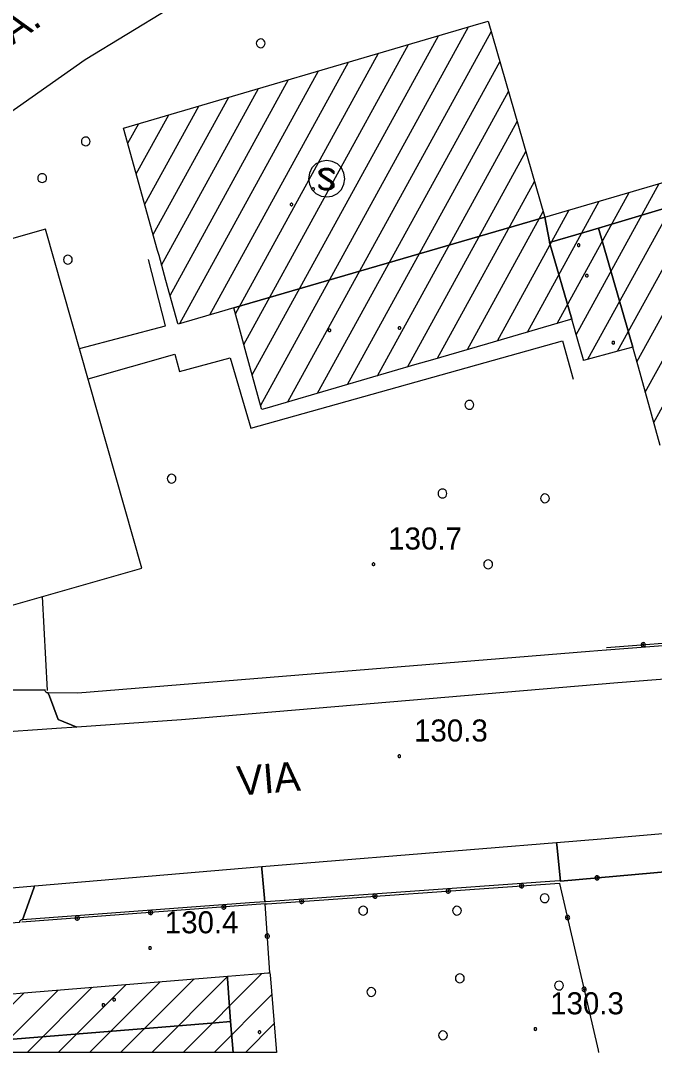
# Model space of a CAD drawing. Extents: x 513373 to 514978, y 5038576 to 5040180.
# Drawn here: x 513408.3 to 513451.4, y 5038580.1 to 5038650.3 of the extents above; entities that cross this region are included whole.
import ezdxf

# ---------------------------------------------------------------- set-up
doc = ezdxf.new("R2010")
doc.units = 0
for name, color, linetype in [('2010300', 7, 'Continuous'), ('3010204', 7, 'Continuous'), ('3030201', 7, 'Continuous'), ('3060104', 7, 'Continuous'), ('B1211', 7, 'Continuous'), ('C1131', 7, 'Continuous'), ('C12211', 7, 'Continuous'), ('C2911', 7, 'Continuous'), ('CAMP_C12211', 7, 'Continuous'), ('Default', 7, 'Continuous'), ('F12107', 7, 'Continuous'), ('F12131', 7, 'Continuous'), ('F12132', 7, 'Continuous'), ('G4315', 7, 'Continuous'), ('TOP500', 7, 'Continuous'), ('TOP920', 7, 'Continuous')]:
    doc.layers.add(name, color=color, linetype=linetype)

# ---------------------------------------------------------------- blocks, each defined once
blk = doc.blocks.new('CAMP_1CE415D7')
at = {"layer": 'CAMP_C12211'}
for p, q in [((2.937, -2.063), (7.928, 2.928)), ((5.058, -2.063), (10.238, 3.116)), ((7.18, -2.063), (12.549, 3.306)), ((-5.548, -2.063), (-1.311, 2.174)), ((-3.427, -2.063), (0.999, 2.362)), ((-1.306, -2.063), (3.309, 2.551)), ((0.816, -2.063), (5.618, 2.739)), ((-11.619, 0.351), (-10.551, 1.42)), ((-11.442, -1.593), (-8.241, 1.608)), ((-9.791, -2.063), (-5.931, 1.797)), ((-7.669, -2.063), (-3.621, 1.986)), ((9.301, -2.063), (13.227, 1.863)), ((11.422, -2.063), (13.385, -0.1)), ((-11.912, -2.063), (-11.599, -1.75))]:
    blk.add_line(p, q, dxfattribs=at)
blk = doc.blocks.new('CAMP_2F84D089')
at = {"layer": 'CAMP_C12211'}
for p, q in [((-57.724, -31.968), (-43.578, -6.238)), ((-58.296, -29.896), (-45.619, -6.835)), ((-55.887, -31.74), (-42.047, -6.566)), ((-58.869, -27.824), (-47.659, -7.433)), ((-59.441, -25.752), (-49.699, -8.031)), ((-61.191, -25.821), (-51.74, -8.629)), ((-53.849, -31.147), (-41.456, -8.604)), ((-63.23, -26.415), (-53.78, -9.227)), ((-64.463, -22.431), (-57.861, -10.422)), ((-63.889, -24.5), (-55.821, -9.824)), ((-65.037, -20.361), (-59.901, -11.02)), ((-51.811, -30.553), (-40.865, -10.642)), ((-65.611, -18.292), (-61.942, -11.618)), ((-66.185, -16.222), (-63.982, -12.216)), ((-66.759, -14.153), (-66.022, -12.813)), ((-49.772, -29.959), (-40.273, -12.68)), ((-30.984, -33.147), (-20.405, -13.904)), ((-47.734, -29.365), (-39.682, -14.718)), ((-31.557, -31.075), (-22.446, -14.502)), ((-32.13, -29.004), (-24.486, -15.099)), ((-33.448, -28.287), (-26.526, -15.697)), ((-45.696, -28.772), (-39.091, -16.756)), ((-35.462, -28.837), (-28.566, -16.294)), ((-37.544, -26.397), (-32.647, -17.489)), ((-36.258, -27.171), (-30.606, -16.892)), ((-39.582, -26.99), (-34.687, -18.087)), ((-43.658, -28.178), (-38.499, -18.794)), ((-41.62, -27.584), (-36.727, -18.684))]:
    blk.add_line(p, q, dxfattribs=at)
blk = doc.blocks.new('03080200')
at = {"layer": 'Default'}
for p, q in [((-0.139, 0.046), (-0.146, 0)), ((-0.146, 0), (-0.139, -0.046)), ((-0.118, 0.086), (-0.139, 0.046)), ((-0.086, 0.118), (-0.118, 0.086)), ((-0.046, 0.139), (-0.086, 0.118)), ((0, 0.146), (-0.046, 0.139)), ((-0.042, 0.014), (-0.045, 0)), ((-0.045, 0), (-0.042, -0.014)), ((-0.036, 0.026), (-0.042, 0.014)), ((-0.026, 0.036), (-0.036, 0.026)), ((-0.014, 0.042), (-0.026, 0.036)), ((0, 0.045), (-0.014, 0.042)), ((0.046, 0.139), (0, 0.146)), ((0.014, 0.042), (0, 0.045)), ((0.026, 0.036), (0.014, 0.042)), ((0.036, 0.026), (0.026, 0.036)), ((0.042, 0.014), (0.036, 0.026)), ((0.045, 0), (0.042, 0.014)), ((0.042, -0.014), (0.045, 0)), ((0.086, 0.118), (0.046, 0.139)), ((0.118, 0.086), (0.086, 0.118)), ((0.139, 0.046), (0.118, 0.086)), ((0.146, 0), (0.139, 0.046)), ((0.139, -0.046), (0.146, 0)), ((-0.139, -0.046), (-0.118, -0.086)), ((-0.118, -0.086), (-0.086, -0.118)), ((-0.086, -0.118), (-0.046, -0.139)), ((-0.046, -0.139), (0, -0.146)), ((-0.042, -0.014), (-0.036, -0.026)), ((-0.036, -0.026), (-0.026, -0.036)), ((-0.026, -0.036), (-0.014, -0.042)), ((-0.014, -0.042), (0, -0.045)), ((0, -0.045), (0.014, -0.042)), ((0, -0.146), (0.046, -0.139)), ((0.014, -0.042), (0.026, -0.036)), ((0.026, -0.036), (0.036, -0.026)), ((0.036, -0.026), (0.042, -0.014)), ((0.046, -0.139), (0.086, -0.118)), ((0.086, -0.118), (0.118, -0.086)), ((0.118, -0.086), (0.139, -0.046))]:
    blk.add_line(p, q, dxfattribs=at)
blk = doc.blocks.new('08020400')
at = {"layer": 'Default'}
for p, q in [((-0.086, 0.028), (-0.09, 0)), ((-0.09, 0), (-0.086, -0.028)), ((-0.073, 0.053), (-0.086, 0.028)), ((-0.053, 0.073), (-0.073, 0.053)), ((-0.028, 0.086), (-0.053, 0.073)), ((0, 0.09), (-0.028, 0.086)), ((0.028, 0.086), (0, 0.09)), ((0.053, 0.073), (0.028, 0.086)), ((0.073, 0.053), (0.053, 0.073)), ((0.086, 0.028), (0.073, 0.053)), ((0.09, 0), (0.086, 0.028)), ((0.086, -0.028), (0.09, 0)), ((-0.086, -0.028), (-0.073, -0.053)), ((-0.073, -0.053), (-0.053, -0.073)), ((-0.053, -0.073), (-0.028, -0.086)), ((-0.028, -0.086), (0, -0.09)), ((0, -0.09), (0.028, -0.086)), ((0.028, -0.086), (0.053, -0.073)), ((0.053, -0.073), (0.073, -0.053)), ((0.073, -0.053), (0.086, -0.028))]:
    blk.add_line(p, q, dxfattribs=at)
blk = doc.blocks.new('NSIMB25')
at = {"layer": 'Default'}
for p, q in [((-0.086, 0.028), (-0.09, 0)), ((-0.09, 0), (-0.086, -0.028)), ((-0.073, 0.053), (-0.086, 0.028)), ((-0.053, 0.073), (-0.073, 0.053)), ((-0.028, 0.086), (-0.053, 0.073)), ((0, 0.09), (-0.028, 0.086)), ((0.028, 0.086), (0, 0.09)), ((0.053, 0.073), (0.028, 0.086)), ((0.073, 0.053), (0.053, 0.073)), ((0.086, 0.028), (0.073, 0.053)), ((0.09, 0), (0.086, 0.028)), ((0.086, -0.028), (0.09, 0)), ((-0.086, -0.028), (-0.073, -0.053)), ((-0.073, -0.053), (-0.053, -0.073)), ((-0.053, -0.073), (-0.028, -0.086)), ((-0.028, -0.086), (0, -0.09)), ((0, -0.09), (0.028, -0.086)), ((0.028, -0.086), (0.053, -0.073)), ((0.053, -0.073), (0.073, -0.053)), ((0.073, -0.053), (0.086, -0.028))]:
    blk.add_line(p, q, dxfattribs=at)
blk = doc.blocks.new('05010100')
at = {"layer": 'Default'}
for p, q in [((-0.143, 0.046), (-0.15, 0)), ((-0.15, 0), (-0.143, -0.046)), ((-0.121, 0.088), (-0.143, 0.046)), ((-0.088, 0.121), (-0.121, 0.088)), ((-0.046, 0.143), (-0.088, 0.121)), ((0, 0.15), (-0.046, 0.143)), ((0.046, 0.143), (0, 0.15)), ((0.088, 0.121), (0.046, 0.143)), ((0.121, 0.088), (0.088, 0.121)), ((0.143, 0.046), (0.121, 0.088)), ((0.15, 0), (0.143, 0.046)), ((0.143, -0.046), (0.15, 0)), ((-0.143, -0.046), (-0.121, -0.088)), ((-0.121, -0.088), (-0.088, -0.121)), ((-0.088, -0.121), (-0.046, -0.143)), ((-0.046, -0.143), (0, -0.15)), ((0, -0.15), (0.046, -0.143)), ((0.046, -0.143), (0.088, -0.121)), ((0.088, -0.121), (0.121, -0.088)), ((0.121, -0.088), (0.143, -0.046))]:
    blk.add_line(p, q, dxfattribs=at)
blk = doc.blocks.new('03030201')
at = {"layer": 'Default'}
for p, q in [((-1.001, 0.728), (-1.177, 0.382)), ((-0.728, 1.001), (-1.001, 0.728)), ((-0.382, 1.177), (-0.728, 1.001)), ((0, 1.237), (-0.382, 1.177)), ((-0.368, 0.643), (-0.158, 0.718)), ((-0.158, 0.718), (0.127, 0.718)), ((0.382, 1.177), (0, 1.237)), ((0.127, 0.718), (0.337, 0.643)), ((0.728, 1.001), (0.382, 1.177)), ((1.001, 0.728), (0.728, 1.001)), ((1.177, 0.382), (1.001, 0.728)), ((-1.177, 0.382), (-1.238, 0)), ((-1.238, 0), (-1.177, -0.382)), ((-0.518, 0.508), (-0.368, 0.643)), ((-0.518, 0.358), (-0.518, 0.508)), ((-0.443, 0.223), (-0.518, 0.358)), ((-0.333, 0.584), (-0.451, 0.478)), ((-0.451, 0.478), (-0.451, 0.376)), ((-0.451, 0.376), (-0.389, 0.265)), ((-0.368, 0.148), (-0.443, 0.223)), ((-0.389, 0.265), (-0.326, 0.201)), ((-0.298, 0.526), (-0.383, 0.448)), ((-0.383, 0.448), (-0.383, 0.394)), ((-0.383, 0.394), (-0.335, 0.306)), ((0.148, -0.186), (-0.368, 0.148)), ((-0.335, 0.306), (-0.287, 0.257)), ((-0.147, 0.651), (-0.333, 0.584)), ((-0.326, 0.201), (0.183, -0.128)), ((-0.135, 0.583), (-0.298, 0.526)), ((-0.287, 0.257), (-0.18, 0.198)), ((-0.18, 0.198), (0.337, -0.137)), ((0.115, 0.651), (-0.147, 0.651)), ((0.103, 0.583), (-0.135, 0.583)), ((0.266, 0.526), (0.103, 0.583)), ((0.301, 0.584), (0.115, 0.651)), ((0.487, 0.327), (0.266, 0.526)), ((0.487, 0.418), (0.301, 0.584)), ((0.337, 0.643), (0.487, 0.508)), ((0.487, 0.508), (0.487, 0.327)), ((1.238, 0), (1.177, 0.382)), ((1.177, -0.382), (1.238, 0)), ((-1.177, -0.382), (-1.001, -0.728)), ((-0.518, -0.39), (-0.298, -0.588)), ((-0.518, -0.572), (-0.518, -0.39)), ((-0.333, -0.647), (-0.518, -0.481)), ((-0.368, -0.707), (-0.518, -0.572)), ((-0.147, -0.714), (-0.333, -0.647)), ((-0.298, -0.588), (-0.135, -0.647)), ((-0.135, -0.647), (0.103, -0.647)), ((0.103, -0.647), (0.266, -0.588)), ((0.301, -0.647), (0.115, -0.714)), ((0.254, -0.245), (0.148, -0.186)), ((0.183, -0.128), (0.295, -0.191)), ((0.302, -0.293), (0.254, -0.245)), ((0.266, -0.588), (0.352, -0.512)), ((0.295, -0.191), (0.357, -0.253)), ((0.419, -0.542), (0.301, -0.647)), ((0.352, -0.382), (0.302, -0.293)), ((0.337, -0.137), (0.412, -0.212)), ((0.487, -0.572), (0.337, -0.707)), ((0.352, -0.512), (0.352, -0.382)), ((0.357, -0.253), (0.419, -0.364)), ((0.412, -0.212), (0.487, -0.347)), ((0.419, -0.364), (0.419, -0.542)), ((0.487, -0.347), (0.487, -0.572)), ((1.001, -0.728), (1.177, -0.382)), ((-1.001, -0.728), (-0.728, -1.001)), ((-0.728, -1.001), (-0.382, -1.177)), ((-0.382, -1.177), (0, -1.238)), ((-0.158, -0.782), (-0.368, -0.707)), ((0.127, -0.782), (-0.158, -0.782)), ((0.115, -0.714), (-0.147, -0.714)), ((0, -1.238), (0.382, -1.177)), ((0.337, -0.707), (0.127, -0.782)), ((0.382, -1.177), (0.728, -1.001)), ((0.728, -1.001), (1.001, -0.728))]:
    blk.add_line(p, q, dxfattribs=at)
blk = doc.blocks.new('A$C3704598A')
at = {"layer": '2010300'}
for points in [[(63.875, -708.514), (65.701, -714.881), (66.154, -716.461), (50.099, -726.135), (45.283, -729.066), (39.595, -732.528), (29.764, -739.427), (17.578, -748.279), (17.196, -748.707), (8.795, -758.134), (8.774, -758.179), (8.768, -758.22), (8.774, -758.259)], [(36.874, -775.359), (36.871, -775.404), (36.88, -775.442), (36.895, -775.472), (36.907, -775.486), (36.914, -775.495), (36.941, -775.516), (36.972, -775.531), (37.005, -775.537), (37.076, -775.539), (39.113, -775.552), (73.91, -772.72), (75.04, -772.628)], [(71.944, -788.357), (71.911, -788.346), (71.882, -788.343), (70.906, -788.412), (51.893, -789.76)]]:
    blk.add_lwpolyline(points, dxfattribs=at)
at = {"layer": '3010204'}
for points in [[(39.213, -752.142), (45.068, -750.604), (43.911, -746.101)], [(39.803, -754.209), (45.701, -752.536), (46.027, -753.7), (49.467, -752.772), (50.865, -757.55), (72.079, -751.622), (72.799, -754.221)], [(36.69, -769.003), (37.019, -775.389)]]:
    blk.add_lwpolyline(points, dxfattribs=at)
at = {"layer": '3060104'}
blk.add_lwpolyline([(23.688, -747.789), (30.258, -770.837), (43.469, -767.071), (36.899, -744.023), (23.688, -747.789)], dxfattribs=at)
at = {"layer": 'B1211'}
blk.add_lwpolyline([(182.854, -779.395), (110.289, -784.942), (71.944, -788.357), (71.695, -785.89), (71.68, -785.737), (74.707, -785.49), (148.809, -779.036), (181.633, -776.874)], dxfattribs=at)
for points in [[(126.207, -770.822), (125.282, -770.893), (121.262, -771.205), (105.455, -772.523), (91.204, -773.673), (75.853, -774.87), (46.166, -777.392), (39.03, -777.882), (37.775, -777.377), (37.169, -775.785), (37.076, -775.539), (39.113, -775.552), (73.91, -772.72), (75.04, -772.628), (75.078, -772.63), (82.766, -772.041), (100.88, -770.652), (125.459, -768.701), (126.353, -768.63), (126.388, -768.62), (126.591, -769.326), (126.566, -770.204)], [(36.874, -775.359), (36.871, -775.404), (36.88, -775.442), (36.895, -775.472), (36.907, -775.486), (36.914, -775.495), (36.941, -775.516), (36.972, -775.531), (37.005, -775.537), (37.076, -775.539), (37.169, -775.785), (37.775, -777.377), (39.03, -777.882), (37.652, -777.977), (33.075, -778.291), (34.323, -775.598), (34.359, -775.521), (34.445, -775.519), (34.49, -775.507), (34.525, -775.485), (34.556, -775.448), (34.572, -775.409), (34.576, -775.359), (35.967, -775.359)], [(71.944, -788.357), (71.911, -788.346), (71.882, -788.343), (70.906, -788.412), (51.893, -789.76), (51.852, -789.755), (51.821, -789.758), (51.629, -787.527), (51.616, -787.372), (71.68, -785.737), (71.695, -785.89)], [(51.821, -789.758), (50.787, -789.835), (35.341, -790.991), (36.103, -788.834), (36.159, -788.677), (51.616, -787.372), (51.629, -787.527)], [(35.341, -790.991), (35.266, -790.997), (35.233, -791.006), (35.199, -791.024), (35.167, -791.055), (35.152, -791.08), (35.141, -791.112), (35.14, -791.17), (34.228, -791.241), (32.804, -791.349), (32.793, -791.289), (32.773, -791.253), (32.74, -791.221), (32.703, -791.202), (32.662, -791.195), (32.594, -791.198), (31.771, -789.207), (31.711, -789.061), (36.159, -788.677), (36.103, -788.834)]]:
    blk.add_lwpolyline(points, close=True, dxfattribs=at)
at = {"layer": 'C1131'}
for points in [[(70.879, -743.211), (69.869, -743.505), (49.715, -749.383), (48.71, -749.676), (47.244, -750.104), (45.921, -750.489), (45.906, -750.435), (45.1, -747.529), (44.628, -745.825), (44.53, -745.472), (42.222, -737.153), (66.009, -730.184), (67.014, -729.89), (70.863, -743.155)], [(112.295, -732.614), (111.902, -732.735), (111.351, -732.904), (98.666, -736.811), (99.057, -738.153), (85.626, -742.147), (85.609, -742.087), (85.22, -740.763), (84.217, -741.064), (74.53, -743.966), (73.524, -744.256), (71.2, -744.928), (71.19, -744.875), (70.879, -743.211), (72.044, -742.87), (110.878, -731.497), (111.883, -731.202), (112.235, -732.406)], [(71.2, -744.928), (72.706, -750.151), (72.62, -750.176), (71.701, -750.444), (66.966, -751.823), (63.085, -752.954), (62.175, -753.219), (51.959, -756.195), (51.624, -756.292), (51.609, -756.238), (50.568, -752.469), (50.168, -751.023), (49.715, -749.383), (69.869, -743.505), (70.879, -743.211), (71.19, -744.875)], [(76.86, -752.044), (75.85, -752.32), (73.515, -752.957), (73.504, -752.92), (73.141, -751.659), (72.706, -750.151), (71.2, -744.928), (73.524, -744.256), (74.53, -743.966)], [(52.201, -794.733), (52.625, -800), (49.671, -800), (49.495, -797.911), (49.287, -794.978), (49.277, -794.824), (50.991, -794.684), (51.291, -794.659), (52.022, -794.599), (52.172, -794.586)], [(49.495, -797.911), (48.464, -797.994), (27.652, -799.664), (27.389, -796.766), (27.375, -796.612), (32.034, -796.231), (33.066, -796.147), (34.67, -796.016), (35.704, -795.932), (49.277, -794.824), (49.287, -794.978)], [(49.671, -800), (25.469, -800), (25.463, -799.965), (26.624, -799.805), (27.652, -799.664), (48.464, -797.994), (49.495, -797.911)]]:
    blk.add_lwpolyline(points, close=True, dxfattribs=at)
blk.add_lwpolyline([(78.714, -758.737), (77.128, -753.006), (76.86, -752.044), (74.53, -743.966), (84.217, -741.064)], dxfattribs=at)
at = {"layer": 'C12211'}
blk.add_lwpolyline([(78.714, -758.737), (77.128, -753.006), (76.86, -752.044), (75.85, -752.32), (73.515, -752.957), (73.504, -752.92), (73.141, -751.659), (72.706, -750.151), (72.62, -750.176), (71.701, -750.444), (66.966, -751.823), (63.085, -752.954), (62.175, -753.219), (51.959, -756.195), (51.624, -756.292), (51.609, -756.238), (50.568, -752.469), (50.168, -751.023), (49.715, -749.383), (48.71, -749.676), (47.244, -750.104), (45.921, -750.489), (45.906, -750.435), (45.1, -747.529), (44.628, -745.825), (44.53, -745.472), (42.222, -737.153), (66.009, -730.184), (67.014, -729.89), (70.863, -743.155), (70.879, -743.211), (72.044, -742.87), (110.878, -731.497)], dxfattribs=at)
blk.add_lwpolyline([(52.201, -794.733), (52.625, -800), (25.207, -800), (25.463, -799.965), (26.624, -799.805), (27.652, -799.664), (27.389, -796.766), (27.375, -796.612), (32.034, -796.231), (33.066, -796.147), (34.67, -796.016), (35.704, -795.932), (49.277, -794.824), (50.991, -794.684), (51.291, -794.659), (52.022, -794.599), (52.172, -794.586)], close=True, dxfattribs=at)
at = {"layer": 'C2911'}
for points in [[(75.079, -772.481), (81.537, -771.985), (81.84, -771.962), (82.751, -771.892)], [(71.944, -788.357), (110.289, -784.942), (182.854, -779.395)], [(51.841, -789.905), (51.989, -789.895), (71.882, -788.493), (71.886, -788.509), (74.506, -799.857), (74.539, -800.001)], [(52.172, -794.586), (51.863, -790.22), (51.842, -789.929), (51.841, -789.905), (35.287, -791.146)]]:
    blk.add_lwpolyline(points, dxfattribs=at)
at = {"layer": '3030201'}
blk.add_blockref('03030201', (56.035, -740.6), dxfattribs=at)
at = {"layer": 'C2911'}
for p, rotation in [((77.571, -772.289), 4.389252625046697), ((74.435, -788.135), 5.088581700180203), ((64.31, -789.027), 4.031902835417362), ((69.297, -788.675), 4.031902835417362), ((54.334, -789.73), 4.031902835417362), ((59.322, -789.378), 4.031902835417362), ((44.055, -790.489), -175.71362651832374), ((49.041, -790.115), -175.71362651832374), ((39.069, -790.863), -175.71362651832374), ((72.424, -790.839), -76.99973397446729), ((51.995, -792.093), 94.04399656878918), ((73.549, -795.711), -76.99973397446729)]:
    blk.add_blockref('03080200', p, dxfattribs=dict(at, rotation=rotation))
at = {"layer": 'CAMP_C12211'}
for name, p in [('CAMP_2F84D089', (109.269, -724.04)), ('CAMP_1CE415D7', (39.082, -797.937))]:
    blk.add_blockref(name, p, dxfattribs=at)
at = {"layer": 'F12107'}
for p in [(59.218, -766.814), (60.977, -779.866), (44.02, -792.905), (70.235, -798.415)]:
    blk.add_blockref('08020400', p, dxfattribs=at)
at = {"layer": 'F12131'}
for p in [(53.641, -742.353), (73.737, -747.194), (56.225, -750.909), (41.572, -796.422)]:
    blk.add_blockref('NSIMB25', p, dxfattribs=at)
at = {"layer": 'F12132'}
for p in [(55.116, -741.307), (73.179, -745.122), (60.99, -750.754), (75.534, -751.752), (40.842, -796.78), (51.466, -798.623)]:
    blk.add_blockref('NSIMB25', p, dxfattribs=at)
at = {"layer": 'G4315', "xscale": 2, "yscale": 2}
for p in [(51.548, -731.393), (39.644, -738.065), (36.681, -740.558), (38.428, -746.105), (65.744, -755.974), (45.483, -760.991), (63.912, -762.002), (70.885, -762.335), (67.024, -766.815), (70.869, -789.52), (58.516, -790.367), (64.899, -790.365), (65.093, -794.967), (71.846, -795.458), (59.072, -795.894), (63.946, -798.842)]:
    blk.add_blockref('05010100', p, dxfattribs=at)
at = {"layer": 'TOP500'}
for s, rotation, p in [('A.', 34.05122, (34.665, -731.532)), ('VIA', 4.6717, (50.008, -782.55))]:
    blk.add_text(s, height=2, rotation=rotation, dxfattribs=at).set_placement(p)
at = {"layer": 'TOP920'}
for s, p in [('130.7', (60.218, -765.814)), ('130.3', (61.977, -778.866)), ('130.4', (45.02, -791.905)), ('130.3', (71.235, -797.415))]:
    blk.add_text(s, height=1.5, dxfattribs=at).set_placement(p)

msp = doc.modelspace()

# ---------------------------------------------------------------- block references
at = {"layer": 'Default'}
msp.add_blockref('A$C3704598A', (513373.046, 5039380.14), dxfattribs=at)

doc.saveas('drawing.dxf')
